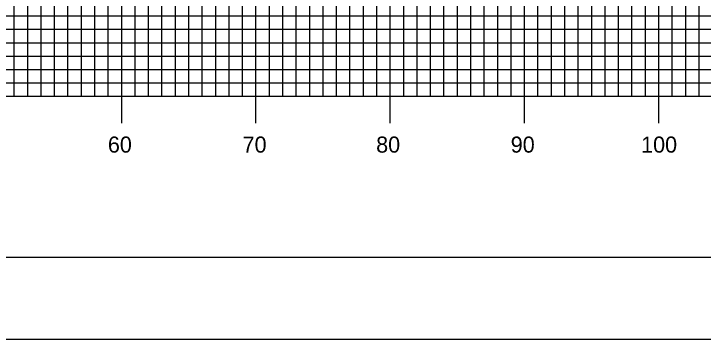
# Model space of a CAD drawing. Extents: x 1782254 to 1782597, y 442591 to 442811.
# Drawn here: x 1782471.4 to 1782522.7, y 442590.5 to 442614.8 of the extents above; entities that cross this region are included whole.
import ezdxf

# ---------------------------------------------------------------- set-up
doc = ezdxf.new("R2010")
doc.units = 0
for name, color, linetype in [('BORDER', 7, 'Continuous'), ('H_V ANNOTATION', 7, 'Continuous'), ('MAJOR', 7, 'Continuous'), ('MINOR', 7, 'Continuous'), ('PLOT BOUNDARY', 7, 'Continuous')]:
    doc.layers.add(name, color=color, linetype=linetype)

msp = doc.modelspace()

# ---------------------------------------------------------------- linework, layer by layer
at = {"layer": 'BORDER'}
msp.add_lwpolyline([(1782269.834, 442596.665), (1782589.834, 442596.665), (1782589.834, 442806.665), (1782269.834, 442806.665)], close=True, dxfattribs=at)
at = {"layer": 'MAJOR'}
for p, q in [((1782479.434, 442608.665), (1782479.434, 442643.665)), ((1782489.434, 442608.665), (1782489.434, 442643.665)), ((1782499.434, 442608.665), (1782499.434, 442643.665)), ((1782509.434, 442608.665), (1782509.434, 442643.665)), ((1782519.434, 442608.665), (1782519.434, 442643.665)), ((1782279.434, 442613.665), (1782559.434, 442613.665)), ((1782279.434, 442608.665), (1782559.434, 442608.665)), ((1782279.434, 442608.665), (1782559.434, 442608.665)), ((1782479.434, 442606.661), (1782479.434, 442608.665)), ((1782489.434, 442606.661), (1782489.434, 442608.665)), ((1782499.434, 442606.661), (1782499.434, 442608.665)), ((1782509.434, 442606.661), (1782509.434, 442608.665)), ((1782519.434, 442606.661), (1782519.434, 442608.665))]:
    msp.add_line(p, q, dxfattribs=at)
at = {"layer": 'MINOR'}
for p, q in [((1782471.434, 442608.665), (1782471.434, 442643.665)), ((1782472.434, 442608.665), (1782472.434, 442643.665)), ((1782473.434, 442608.665), (1782473.434, 442643.665)), ((1782474.434, 442608.665), (1782474.434, 442643.665)), ((1782475.434, 442608.665), (1782475.434, 442643.665)), ((1782476.434, 442608.665), (1782476.434, 442643.665)), ((1782477.434, 442608.665), (1782477.434, 442643.665)), ((1782478.434, 442608.665), (1782478.434, 442643.665)), ((1782480.434, 442608.665), (1782480.434, 442643.665)), ((1782481.434, 442608.665), (1782481.434, 442643.665)), ((1782482.434, 442608.665), (1782482.434, 442643.665)), ((1782483.434, 442608.665), (1782483.434, 442643.665)), ((1782484.434, 442608.665), (1782484.434, 442643.665)), ((1782485.434, 442608.665), (1782485.434, 442643.665)), ((1782486.434, 442608.665), (1782486.434, 442643.665)), ((1782487.434, 442608.665), (1782487.434, 442643.665)), ((1782488.434, 442608.665), (1782488.434, 442643.665)), ((1782490.434, 442608.665), (1782490.434, 442643.665)), ((1782491.434, 442608.665), (1782491.434, 442643.665)), ((1782492.434, 442608.665), (1782492.434, 442643.665)), ((1782493.434, 442608.665), (1782493.434, 442643.665)), ((1782494.434, 442608.665), (1782494.434, 442643.665)), ((1782495.434, 442608.665), (1782495.434, 442643.665)), ((1782496.434, 442608.665), (1782496.434, 442643.665)), ((1782497.434, 442608.665), (1782497.434, 442643.665)), ((1782498.434, 442608.665), (1782498.434, 442643.665)), ((1782500.434, 442608.665), (1782500.434, 442643.665)), ((1782501.434, 442608.665), (1782501.434, 442643.665)), ((1782502.434, 442608.665), (1782502.434, 442643.665)), ((1782503.434, 442608.665), (1782503.434, 442643.665)), ((1782504.434, 442608.665), (1782504.434, 442643.665)), ((1782505.434, 442608.665), (1782505.434, 442643.665)), ((1782506.434, 442608.665), (1782506.434, 442643.665)), ((1782507.434, 442608.665), (1782507.434, 442643.665)), ((1782508.434, 442608.665), (1782508.434, 442643.665)), ((1782510.434, 442608.665), (1782510.434, 442643.665)), ((1782511.434, 442608.665), (1782511.434, 442643.665)), ((1782512.434, 442608.665), (1782512.434, 442643.665)), ((1782513.434, 442608.665), (1782513.434, 442643.665)), ((1782514.434, 442608.665), (1782514.434, 442643.665)), ((1782515.434, 442608.665), (1782515.434, 442643.665)), ((1782516.434, 442608.665), (1782516.434, 442643.665)), ((1782517.434, 442608.665), (1782517.434, 442643.665)), ((1782518.434, 442608.665), (1782518.434, 442643.665)), ((1782520.434, 442608.665), (1782520.434, 442643.665)), ((1782521.434, 442608.665), (1782521.434, 442643.665)), ((1782522.434, 442608.665), (1782522.434, 442643.665)), ((1782279.434, 442614.665), (1782559.434, 442614.665)), ((1782279.434, 442612.665), (1782559.434, 442612.665)), ((1782279.434, 442611.665), (1782559.434, 442611.665)), ((1782279.434, 442610.665), (1782559.434, 442610.665)), ((1782279.434, 442609.665), (1782559.434, 442609.665))]:
    msp.add_line(p, q, dxfattribs=at)
at = {"layer": 'PLOT BOUNDARY'}
msp.add_lwpolyline([(1782253.647, 442590.547), (1782593.647, 442590.547), (1782593.647, 442810.547), (1782253.647, 442810.547)], close=True, dxfattribs=at)

# ---------------------------------------------------------------- texts
at = {"layer": 'H_V ANNOTATION'}
for s, p in [('60', (1782478.406, 442604.465)), ('70', (1782488.438, 442604.465)), ('80', (1782498.385, 442604.465)), ('90', (1782508.406, 442604.465)), ('100', (1782518.117, 442604.465))]:
    msp.add_text(s, height=1.2, dxfattribs=at).set_placement(p)

doc.saveas('drawing.dxf')
